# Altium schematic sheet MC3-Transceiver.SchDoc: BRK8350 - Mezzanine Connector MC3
size C; Author: Casey Smith; Organization: Opal Kelly; Address1: 13500 SW 72nd Ave STE 100; Address2: Portland, OR 97223; Address3: 217.391.3724; Address4: http://www.opalkelly.com; DocumentNumber: xxx; Revision: 1; SheetNumber: 4; SheetTotal: 7
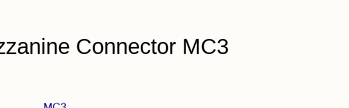
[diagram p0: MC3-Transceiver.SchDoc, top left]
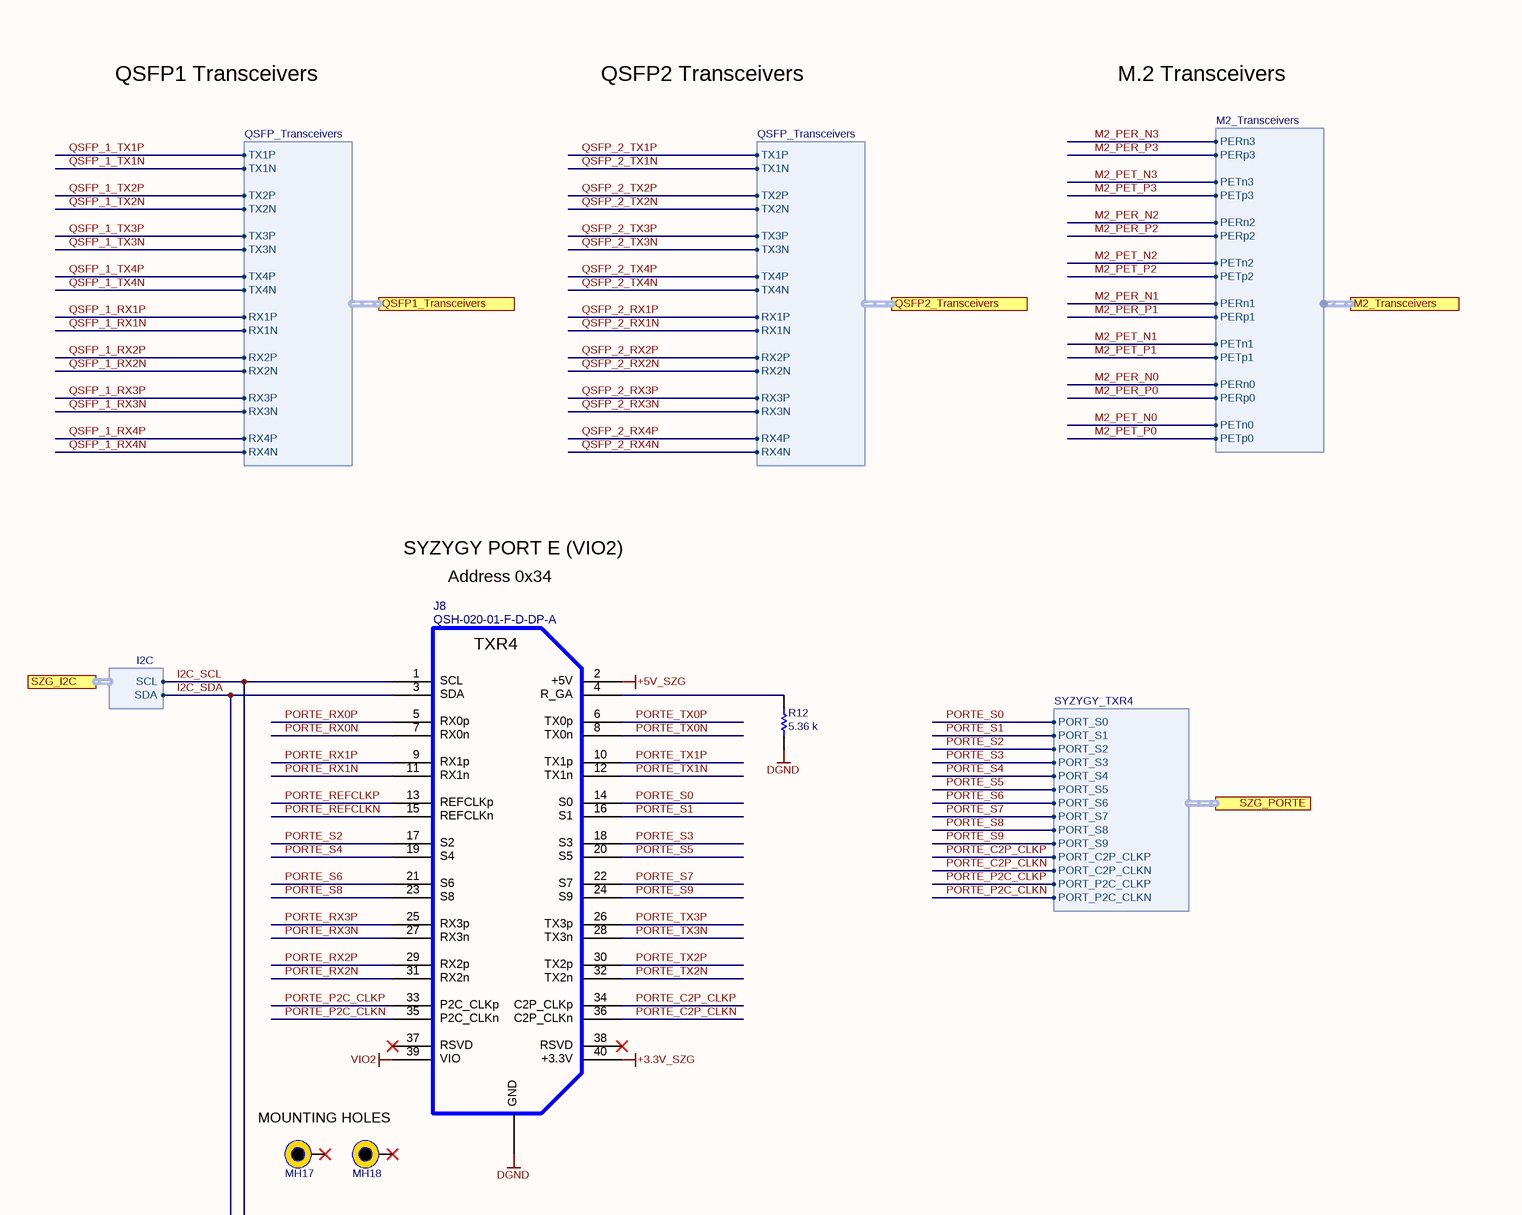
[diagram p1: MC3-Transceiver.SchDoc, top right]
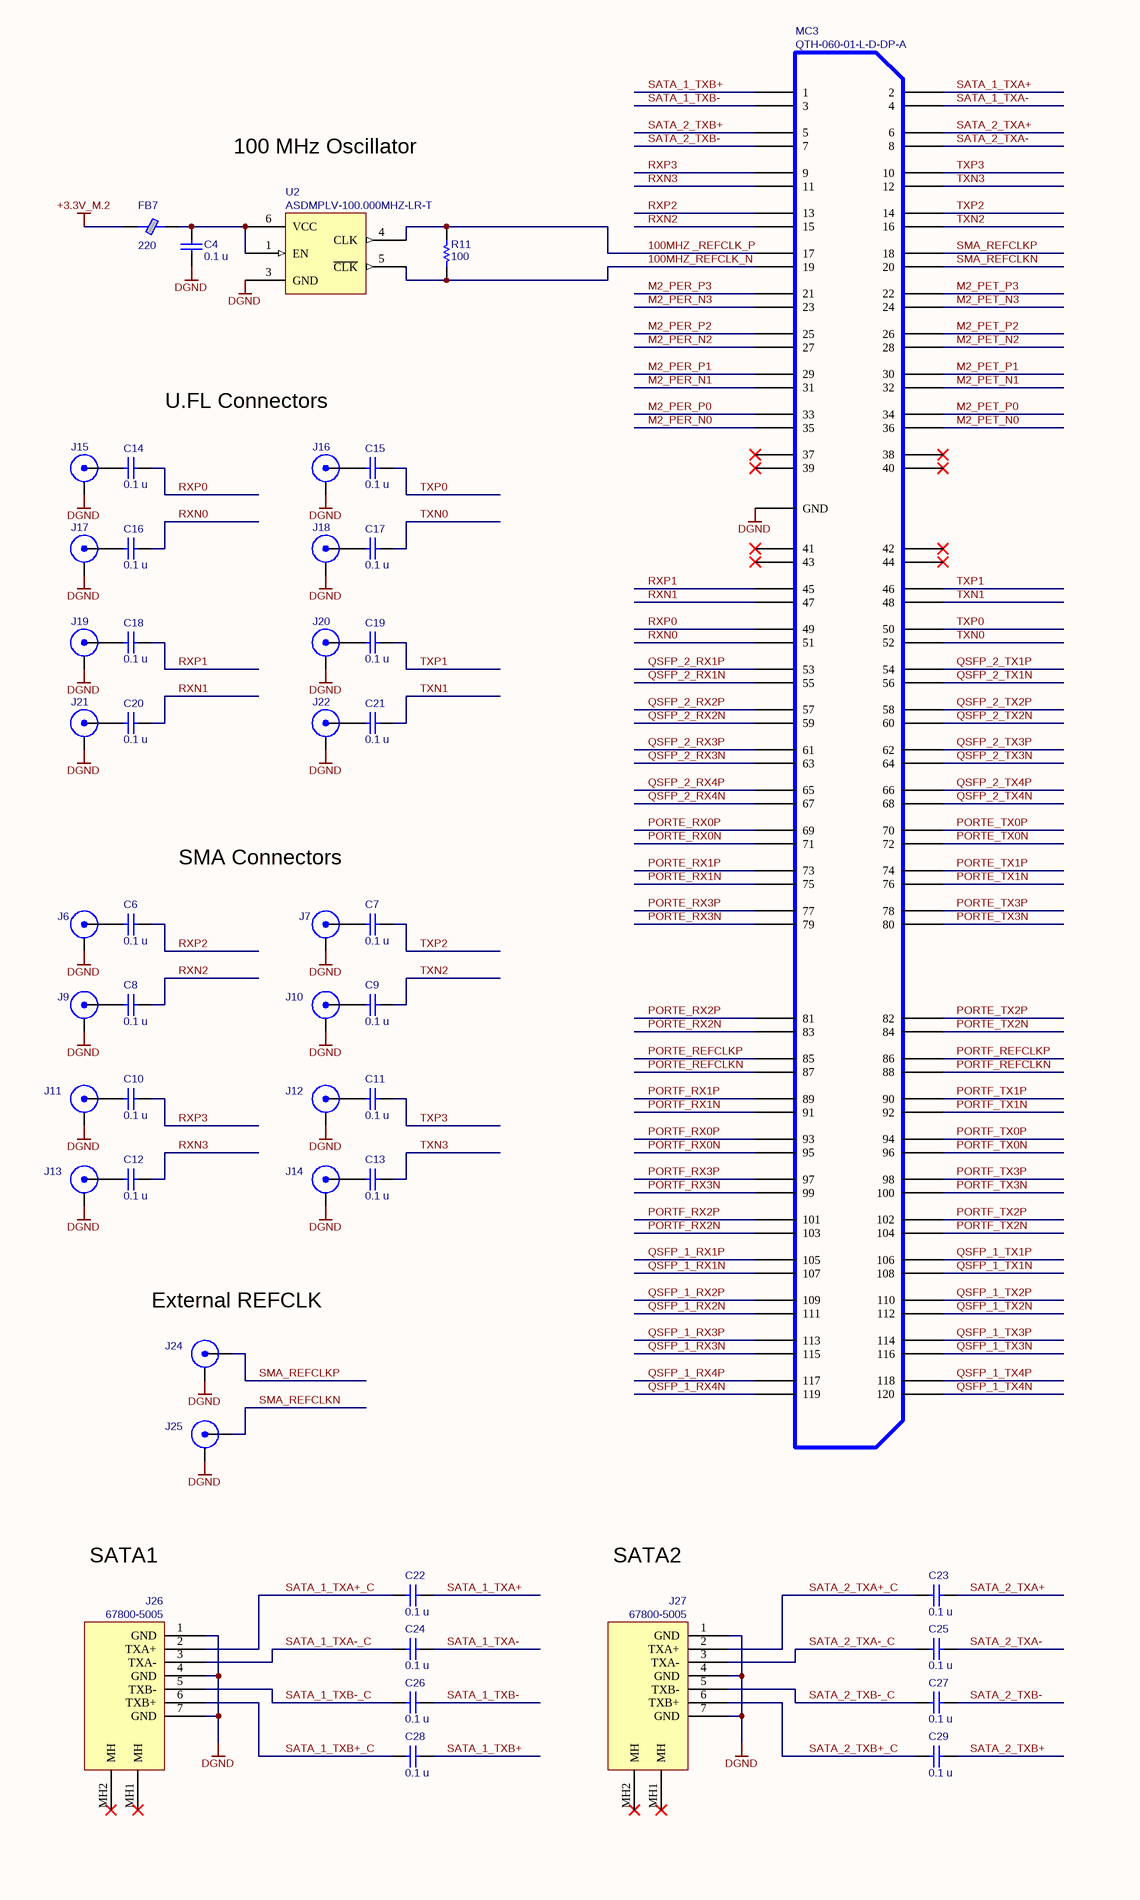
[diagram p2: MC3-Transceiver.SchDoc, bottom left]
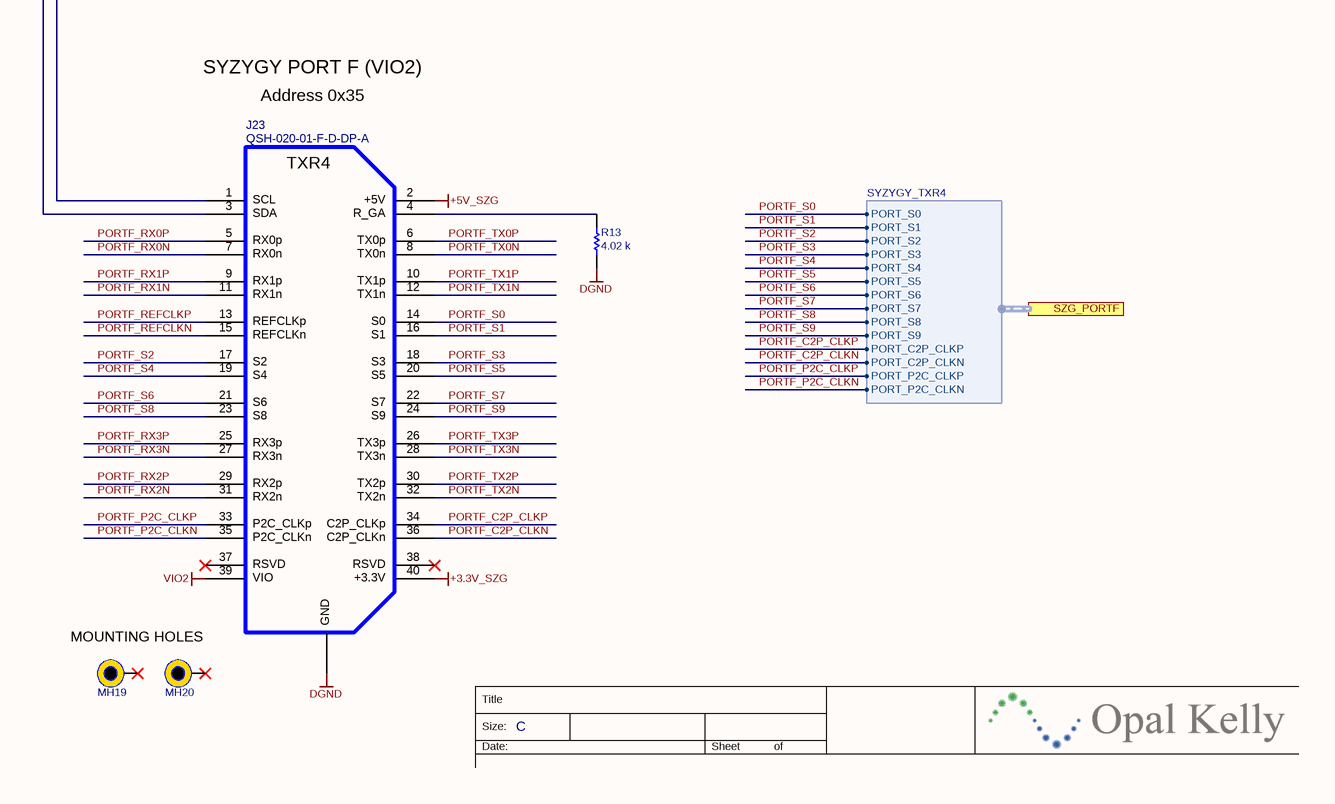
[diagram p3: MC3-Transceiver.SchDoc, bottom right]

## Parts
C4  value 0.1 u  [CAPC1005X06A]  (hidden comment: SM-0402, 10%, 10v)
C6  value 0.1 u  [CAPC1005X06A]  (hidden comment: SM-0402, 10%, 10v)
C7  value 0.1 u  [CAPC1005X06A]  (hidden comment: SM-0402, 10%, 10v)
C8  value 0.1 u  [CAPC1005X06A]  (hidden comment: SM-0402, 10%, 10v)
C9  value 0.1 u  [CAPC1005X06A]  (hidden comment: SM-0402, 10%, 10v)
C10  value 0.1 u  [CAPC1005X06A]  (hidden comment: SM-0402, 10%, 10v)
C11  value 0.1 u  [CAPC1005X06A]  (hidden comment: SM-0402, 10%, 10v)
C12  value 0.1 u  [CAPC1005X06A]  (hidden comment: SM-0402, 10%, 10v)
C13  value 0.1 u  [CAPC1005X06A]  (hidden comment: SM-0402, 10%, 10v)
C14  value 0.1 u  [CAPC1005X06A]  (hidden comment: SM-0402, 10%, 10v)
C15  value 0.1 u  [CAPC1005X06A]  (hidden comment: SM-0402, 10%, 10v)
C16  value 0.1 u  [CAPC1005X06A]  (hidden comment: SM-0402, 10%, 10v)
C17  value 0.1 u  [CAPC1005X06A]  (hidden comment: SM-0402, 10%, 10v)
C18  value 0.1 u  [CAPC1005X06A]  (hidden comment: SM-0402, 10%, 10v)
C19  value 0.1 u  [CAPC1005X06A]  (hidden comment: SM-0402, 10%, 10v)
C20  value 0.1 u  [CAPC1005X06A]  (hidden comment: SM-0402, 10%, 10v)
C21  value 0.1 u  [CAPC1005X06A]  (hidden comment: SM-0402, 10%, 10v)
C22  value 0.1 u  [CAPC1005X06A]  (hidden comment: SM-0402, 10%, 10v)
C23  value 0.1 u  [CAPC1005X06A]  (hidden comment: SM-0402, 10%, 10v)
C24  value 0.1 u  [CAPC1005X06A]  (hidden comment: SM-0402, 10%, 10v)
C25  value 0.1 u  [CAPC1005X06A]  (hidden comment: SM-0402, 10%, 10v)
C26  value 0.1 u  [CAPC1005X06A]  (hidden comment: SM-0402, 10%, 10v)
C27  value 0.1 u  [CAPC1005X06A]  (hidden comment: SM-0402, 10%, 10v)
C28  value 0.1 u  [CAPC1005X06A]  (hidden comment: SM-0402, 10%, 10v)
C29  value 0.1 u  [CAPC1005X06A]  (hidden comment: SM-0402, 10%, 10v)
FB7  value 220  [RESC2012N]  (hidden comment: 220 OHM 2000MA 0805)
J6  RXP2  [SMA]  (value not drawn)
J7  TXP2  [SMA]  (value not drawn)
J8  QSH-020-01-F-D-DP-A  [QSH-020-01-X-D-DP-A-L]
J9  RXN2  [SMA]  (value not drawn)
J10  TXN2  [SMA]  (value not drawn)
J11  RXP3  [SMA]  (value not drawn)
J12  TXP3  [SMA]  (value not drawn)
J13  RXN3  [SMA]  (value not drawn)
J14  TXN3  [SMA]  (value not drawn)
J15  RXP0  [UFL-R-SMT-1]  (value not drawn)
J16  TXP0  [UFL-R-SMT-1]  (value not drawn)
J17  RXN0  [UFL-R-SMT-1]  (value not drawn)
J18  TXN0  [UFL-R-SMT-1]  (value not drawn)
J19  RXP1  [UFL-R-SMT-1]  (value not drawn)
J20  TXP1  [UFL-R-SMT-1]  (value not drawn)
J21  RXN1  [UFL-R-SMT-1]  (value not drawn)
J22  TXN1  [UFL-R-SMT-1]  (value not drawn)
J23  QSH-020-01-F-D-DP-A  [QSH-020-01-X-D-DP-A-L]
J24  REFCLKP  [SMA]  (value not drawn)
J25  REFCLKN  [SMA]  (value not drawn)
J26  67800-5005  [MOLEX-67800-5005]
J27  67800-5005  [MOLEX-67800-5005]
MC3  QTH-060-01-L-D-DP-A  [QTH-060-01-X-D-DP-A]
MH17  MTG  [MTG-3.2/6.5-PTH]  (value not drawn)
MH18  MTG  [MTG-3.2/6.5-PTH]  (value not drawn)
MH19  MTG  [MTG-3.2/6.5-PTH]  (value not drawn)
MH20  MTG  [MTG-3.2/6.5-PTH]  (value not drawn)
R11  value 100  [RESC1005X06A]  (hidden comment: SM-0402, 1%, 1/16W)
R12  value 5.36 k  [RESC1005X06A]  (hidden comment: RC0402FR-075K36L)
R13  value 4.02 k  [RESC1005X06A]  (hidden comment: CRCW04024K02FKED)
U2  ASDMPLV-100.000MHZ-LR-T  [OSC_SMD_25x20]

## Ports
M2_Transceivers (harness M2_Transceivers), QSFP1_Transceivers (harness QSFP_Transceivers), QSFP2_Transceivers (harness QSFP_Transceivers), SZG_I2C (harness I2C), SZG_PORTE (harness SYZYGY_TXR4), SZG_PORTF (harness SYZYGY_TXR4)

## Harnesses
QSFP_Transceivers: TX1P, TX1N, TX2P, TX2N, TX3P, TX3N, TX4P, TX4N, RX1P, RX1N, RX2P, RX2N, RX3P, RX3N, RX4P, RX4N
I2C: SCL, SDA
SYZYGY_TXR4: PORT_S0, PORT_S1, PORT_S2, PORT_S3, PORT_S4, PORT_S5, PORT_S6, PORT_S7, PORT_S8, PORT_S9, PORT_C2P_CLKP, PORT_C2P_CLKN, PORT_P2C_CLKP, PORT_P2C_CLKN
M2_Transceivers: PETn3, PETp3, PERn3, PERp3, PETn2, PETp2, PERn2, PERp2, PETn1, PETp1, PERn1, PERp1, PETn0, PETp0, PERn0, PERp0

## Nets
+3.3V_M.2: FB7.1
+3.3V_SZG: J8.40 J23.40
+5V_SZG: J8.2 J23.2
DGND: C4.1 J6.2(GND) J7.2(GND) J8.0(GND) J9.2(GND) J10.2(GND) J11.2(GND) J12.2(GND) J13.2(GND) J14.2(GND) J15.2(GND) J16.2(GND) J17.2(GND) J18.2(GND) J19.2(GND) J20.2(GND) J21.2(GND) J22.2(GND) J23.0(GND) J24.2(GND) J25.2(GND) J26.1(GND) J26.4(GND) J26.7(GND) J27.1(GND) J27.4(GND) J27.7(GND) MC3.0(GND) R12.1 R13.1 U2.3(GND)
VIO2: J8.39 J23.39
100MHZ _REFCLK_P: MC3.17 R11.2 U2.4(CLK)
100MHZ_REFCLK_N: MC3.19 R11.1 U2.5(~{CLK})
I2C_SCL: J8.1 J23.1 ; port SZG_I2C.SCL
I2C_SDA: J8.3 J23.3 ; port SZG_I2C.SDA
M2_PER_N0: MC3.35 ; port M2_Transceivers.PERn0
M2_PER_N1: MC3.31 ; port M2_Transceivers.PERn1
M2_PER_N2: MC3.27 ; port M2_Transceivers.PERn2
M2_PER_N3: MC3.23 ; port M2_Transceivers.PERn3
M2_PER_P0: MC3.33 ; port M2_Transceivers.PERp0
M2_PER_P1: MC3.29 ; port M2_Transceivers.PERp1
M2_PER_P2: MC3.25 ; port M2_Transceivers.PERp2
M2_PER_P3: MC3.21 ; port M2_Transceivers.PERp3
M2_PET_N0: MC3.36 ; port M2_Transceivers.PETn0
M2_PET_N1: MC3.32 ; port M2_Transceivers.PETn1
M2_PET_N2: MC3.28 ; port M2_Transceivers.PETn2
M2_PET_N3: MC3.24 ; port M2_Transceivers.PETn3
M2_PET_P0: MC3.34 ; port M2_Transceivers.PETp0
M2_PET_P1: MC3.30 ; port M2_Transceivers.PETp1
M2_PET_P2: MC3.26 ; port M2_Transceivers.PETp2
M2_PET_P3: MC3.22 ; port M2_Transceivers.PETp3
PORTE_C2P_CLKN: J8.36 ; port SZG_PORTE.PORT_C2P_CLKN
PORTE_C2P_CLKP: J8.34 ; port SZG_PORTE.PORT_C2P_CLKP
PORTE_P2C_CLKN: J8.35 ; port SZG_PORTE.PORT_P2C_CLKN
PORTE_P2C_CLKP: J8.33 ; port SZG_PORTE.PORT_P2C_CLKP
PORTE_REFCLKN: J8.15 MC3.87
PORTE_REFCLKP: J8.13 MC3.85
PORTE_RX0N: J8.7 MC3.71
PORTE_RX0P: J8.5 MC3.69
PORTE_RX1N: J8.11 MC3.75
PORTE_RX1P: J8.9 MC3.73
PORTE_RX2N: J8.31 MC3.83
PORTE_RX2P: J8.29 MC3.81
PORTE_RX3N: J8.27 MC3.79
PORTE_RX3P: J8.25 MC3.77
PORTE_S0: J8.14 ; port SZG_PORTE.PORT_S0
PORTE_S1: J8.16 ; port SZG_PORTE.PORT_S1
PORTE_S2: J8.17 ; port SZG_PORTE.PORT_S2
PORTE_S3: J8.18 ; port SZG_PORTE.PORT_S3
PORTE_S4: J8.19 ; port SZG_PORTE.PORT_S4
PORTE_S5: J8.20 ; port SZG_PORTE.PORT_S5
PORTE_S6: J8.21 ; port SZG_PORTE.PORT_S6
PORTE_S7: J8.22 ; port SZG_PORTE.PORT_S7
PORTE_S8: J8.23 ; port SZG_PORTE.PORT_S8
PORTE_S9: J8.24 ; port SZG_PORTE.PORT_S9
PORTE_TX0N: J8.8 MC3.72
PORTE_TX0P: J8.6 MC3.70
PORTE_TX1N: J8.12 MC3.76
PORTE_TX1P: J8.10 MC3.74
PORTE_TX2N: J8.32 MC3.84
PORTE_TX2P: J8.30 MC3.82
PORTE_TX3N: J8.28 MC3.80
PORTE_TX3P: J8.26 MC3.78
PORTF_C2P_CLKN: J23.36 ; port SZG_PORTF.PORT_C2P_CLKN
PORTF_C2P_CLKP: J23.34 ; port SZG_PORTF.PORT_C2P_CLKP
PORTF_P2C_CLKN: J23.35 ; port SZG_PORTF.PORT_P2C_CLKN
PORTF_P2C_CLKP: J23.33 ; port SZG_PORTF.PORT_P2C_CLKP
PORTF_REFCLKN: J23.15 MC3.88
PORTF_REFCLKP: J23.13 MC3.86
PORTF_RX0N: J23.7 MC3.95
PORTF_RX0P: J23.5 MC3.93
PORTF_RX1N: J23.11 MC3.91
PORTF_RX1P: J23.9 MC3.89
PORTF_RX2N: J23.31 MC3.103
PORTF_RX2P: J23.29 MC3.101
PORTF_RX3N: J23.27 MC3.99
PORTF_RX3P: J23.25 MC3.97
PORTF_S0: J23.14 ; port SZG_PORTF.PORT_S0
PORTF_S1: J23.16 ; port SZG_PORTF.PORT_S1
PORTF_S2: J23.17 ; port SZG_PORTF.PORT_S2
PORTF_S3: J23.18 ; port SZG_PORTF.PORT_S3
PORTF_S4: J23.19 ; port SZG_PORTF.PORT_S4
PORTF_S5: J23.20 ; port SZG_PORTF.PORT_S5
PORTF_S6: J23.21 ; port SZG_PORTF.PORT_S6
PORTF_S7: J23.22 ; port SZG_PORTF.PORT_S7
PORTF_S8: J23.23 ; port SZG_PORTF.PORT_S8
PORTF_S9: J23.24 ; port SZG_PORTF.PORT_S9
PORTF_TX0N: J23.8 MC3.96
PORTF_TX0P: J23.6 MC3.94
PORTF_TX1N: J23.12 MC3.92
PORTF_TX1P: J23.10 MC3.90
PORTF_TX2N: J23.32 MC3.104
PORTF_TX2P: J23.30 MC3.102
PORTF_TX3N: J23.28 MC3.100
PORTF_TX3P: J23.26 MC3.98
QSFP_1_RX1N: MC3.107 ; port QSFP1_Transceivers.RX1N
QSFP_1_RX1P: MC3.105 ; port QSFP1_Transceivers.RX1P
QSFP_1_RX2N: MC3.111 ; port QSFP1_Transceivers.RX2N
QSFP_1_RX2P: MC3.109 ; port QSFP1_Transceivers.RX2P
QSFP_1_RX3N: MC3.115 ; port QSFP1_Transceivers.RX3N
QSFP_1_RX3P: MC3.113 ; port QSFP1_Transceivers.RX3P
QSFP_1_RX4N: MC3.119 ; port QSFP1_Transceivers.RX4N
QSFP_1_RX4P: MC3.117 ; port QSFP1_Transceivers.RX4P
QSFP_1_TX1N: MC3.108 ; port QSFP1_Transceivers.TX1N
QSFP_1_TX1P: MC3.106 ; port QSFP1_Transceivers.TX1P
QSFP_1_TX2N: MC3.112 ; port QSFP1_Transceivers.TX2N
QSFP_1_TX2P: MC3.110 ; port QSFP1_Transceivers.TX2P
QSFP_1_TX3N: MC3.116 ; port QSFP1_Transceivers.TX3N
QSFP_1_TX3P: MC3.114 ; port QSFP1_Transceivers.TX3P
QSFP_1_TX4N: MC3.120 ; port QSFP1_Transceivers.TX4N
QSFP_1_TX4P: MC3.118 ; port QSFP1_Transceivers.TX4P
QSFP_2_RX1N: MC3.55 ; port QSFP2_Transceivers.RX1N
QSFP_2_RX1P: MC3.53 ; port QSFP2_Transceivers.RX1P
QSFP_2_RX2N: MC3.59 ; port QSFP2_Transceivers.RX2N
QSFP_2_RX2P: MC3.57 ; port QSFP2_Transceivers.RX2P
QSFP_2_RX3N: MC3.63 ; port QSFP2_Transceivers.RX3N
QSFP_2_RX3P: MC3.61 ; port QSFP2_Transceivers.RX3P
QSFP_2_RX4N: MC3.67 ; port QSFP2_Transceivers.RX4N
QSFP_2_RX4P: MC3.65 ; port QSFP2_Transceivers.RX4P
QSFP_2_TX1N: MC3.56 ; port QSFP2_Transceivers.TX1N
QSFP_2_TX1P: MC3.54 ; port QSFP2_Transceivers.TX1P
QSFP_2_TX2N: MC3.60 ; port QSFP2_Transceivers.TX2N
QSFP_2_TX2P: MC3.58 ; port QSFP2_Transceivers.TX2P
QSFP_2_TX3N: MC3.64 ; port QSFP2_Transceivers.TX3N
QSFP_2_TX3P: MC3.62 ; port QSFP2_Transceivers.TX3P
QSFP_2_TX4N: MC3.68 ; port QSFP2_Transceivers.TX4N
QSFP_2_TX4P: MC3.66 ; port QSFP2_Transceivers.TX4P
RXN0: C16.2 MC3.51
RXN1: C20.2 MC3.47
RXN2: C8.2 MC3.15
RXN3: C12.2 MC3.11
RXP0: C14.2 MC3.49
RXP1: C18.2 MC3.45
RXP2: C6.2 MC3.13
RXP3: C10.2 MC3.9
SATA_1_TXA+: C22.2 MC3.2
SATA_1_TXA+_C: C22.1 J26.2(TXA+)
SATA_1_TXA-: C24.2 MC3.4
SATA_1_TXA-_C: C24.1 J26.3(TXA-)
SATA_1_TXB+: C28.2 MC3.1
SATA_1_TXB+_C: C28.1 J26.6(TXB+)
SATA_1_TXB-: C26.2 MC3.3
SATA_1_TXB-_C: C26.1 J26.5(TXB-)
SATA_2_TXA+: C23.2 MC3.6
SATA_2_TXA+_C: C23.1 J27.2(TXA+)
SATA_2_TXA-: C25.2 MC3.8
SATA_2_TXA-_C: C25.1 J27.3(TXA-)
SATA_2_TXB+: C29.2 MC3.5
SATA_2_TXB+_C: C29.1 J27.6(TXB+)
SATA_2_TXB-: C27.2 MC3.7
SATA_2_TXB-_C: C27.1 J27.5(TXB-)
SMA_REFCLKN: J25.1(SIGNAL) MC3.20
SMA_REFCLKP: J24.1(SIGNAL) MC3.18
TXN0: C17.2 MC3.52
TXN1: C21.2 MC3.48
TXN2: C9.2 MC3.16
TXN3: C13.2 MC3.12
TXP0: C15.2 MC3.50
TXP1: C19.2 MC3.46
TXP2: C7.2 MC3.14
TXP3: C11.2 MC3.10
NetC4_2: C4.2 FB7.2 U2.1(EN) U2.6(VCC)
NetC6_1: C6.1 J6.1(SIGNAL)
NetC7_1: C7.1 J7.1(SIGNAL)
NetC8_1: C8.1 J9.1(SIGNAL)
NetC9_1: C9.1 J10.1(SIGNAL)
NetC10_1: C10.1 J11.1(SIGNAL)
NetC11_1: C11.1 J12.1(SIGNAL)
NetC12_1: C12.1 J13.1(SIGNAL)
NetC13_1: C13.1 J14.1(SIGNAL)
NetC14_1: C14.1 J15.1(SIGNAL)
NetC15_1: C15.1 J16.1(SIGNAL)
NetC16_1: C16.1 J17.1(SIGNAL)
NetC17_1: C17.1 J18.1(SIGNAL)
NetC18_1: C18.1 J19.1(SIGNAL)
NetC19_1: C19.1 J20.1(SIGNAL)
NetC20_1: C20.1 J21.1(SIGNAL)
NetC21_1: C21.1 J22.1(SIGNAL)
NetJ8_4: J8.4 R12.2
NetJ23_4: J23.4 R13.2

Not connected (* = marked no-connect by the designer): J8 37* 38*; J23 37* 38*; J26 MH1(MH)* MH2(MH)*; J27 MH1(MH)* MH2(MH)*; MC3 37* 38* 39* 40* 41* 42* 43* 44*; MH17 1*; MH18 1*; MH19 1*; MH20 1*

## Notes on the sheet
- Mezzanine Connector MC3
- QSFP1 Transceivers
- QSFP2 Transceivers
- M.2 Transceivers
- 100 MHz Oscillator
- U.FL Connectors
- Address 0x34
- SYZYGY PORT E (VIO2)
- SMA Connectors
- MOUNTING HOLES
- SYZYGY PORT F (VIO2)
- Address 0x35
- (near J24) External REFCLK
- SATA1
- SATA2
- Title
- Size:
- Date:
- C
- Sheet
- of

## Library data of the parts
C4 C6-C29 = 000070: Partnumber: 000070; manufacturer: Kemet; manufacturer_pn: C0402C104K8PACTU; ValueFloat: 1E-7; id: 750; inventory_price: 0.0023; reorder_quantity: 70000; x_tolerance: 10
FB7 = 000783: Partnumber: 000783; manufacturer: Murata; manufacturer_pn: BLM21PG221SN1D; id: 12845; inventory_price: 0.02; reorder_quantity: 4000
J6 J7 J9-J14 J24 J25 = 000974: Straight SMA PCB Mount; Manufacturer: Amphenol; Manufacturer_PN: 901-144-8RFX; partnumber: 000974
J8 J23 = 000694: 0.5mm Double Row High Speed Socket Assembly; Partnumber: 000694; manufacturer: Samtec
J15-J22 = 001335: U.FL surface-mount coaxial connector; Manufacturer: Hirose; Manufacturer_PN: U.FL-R-SMT-1; partnumber: 001335; x_lifecycle_status: Production
J26 J27 = 000988: SATA 7-pin receptacle; Manufacturer: Molex; partnumber: 000988; Description 2: Vertical Mount, SMD, Latch, 15u Gold; x_lifecycle_status: Production
MC3 = 001769: Partnumber: 001769; manufacturer: Samtec
MH17-MH20 = MTG: Mounting hole; partnumber: ALIGNI_IGNORE
R11 = 000827: Partnumber: 000827; manufacturer: Vishay; manufacturer_pn: CRCW0402100RFKED; id: 13742; inventory_price: 0.0016; reorder_quantity: 2000; x_tolerance: 1
R12 = Resistor: Thick-film resistor; manufacturer: Yageo; partnumber: 001910; ValueFloat: 5360.0
R13 = Resistor: Thick-film resistor; manufacturer: Vishay; partnumber: 001007; ValueFloat: 4020.0
U2 = 001241: Partnumber: 001241; manufacturer: Abracon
